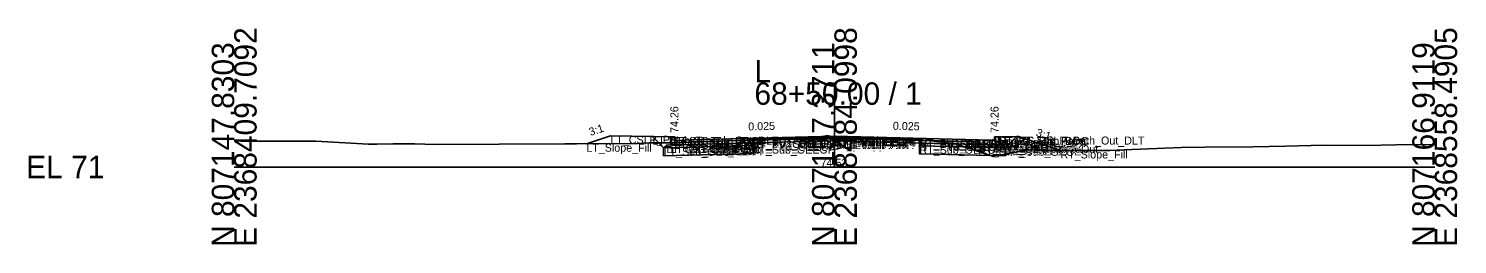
# Model space of a CAD drawing. Extents: x -26 to 8153, y -10 to 9520.
# Drawn here: x 5974.3 to 6152.8, y 8990.3 to 9017.3 of the extents above; entities that cross this region are included whole.
import ezdxf

# ---------------------------------------------------------------- set-up
doc = ezdxf.new("R2010")
doc.units = 0
for name, color, linetype in [('Exist CMT Pavement', 7, 'Continuous'), ('Exist Cross Section Cell', 7, 'Continuous'), ('Exist XS Center Line Elevation Label', 7, 'Continuous'), ('Exist XS Ground Line', 7, 'Continuous'), ('Prop CMT Conc Surface', 7, 'Continuous'), ('Prop CMT Concrete Structures', 7, 'Continuous'), ('Prop CMT Pvmt Course 1', 7, 'Continuous'), ('Prop CMT Pvmt Course 1 CG', 7, 'Continuous'), ('Prop CMT Pvmt Course 1 Wedge', 7, 'Continuous'), ('Prop CMT Pvmt Course 2', 7, 'Continuous'), ('Prop CMT Pvmt Course 2 Wedge', 7, 'Continuous'), ('Prop CMT Pvmt Course 3', 7, 'Continuous'), ('Prop CMT Pvmt Course 3 Wedge', 7, 'Continuous'), ('Prop CMT Pvmt Surface', 7, 'Continuous'), ('Prop CMT Pvmt Wedge Surface 1', 7, 'Continuous'), ('Prop CMT Pvmt Wedge Surface 2', 7, 'Continuous'), ('Prop CMT Pvmt Wedge Surface 3', 7, 'Continuous'), ('Prop CMT Shallow Undercut', 7, 'Continuous'), ('Prop CMT Shallow Undercut Boundary', 7, 'Continuous'), ('Prop CMT Slope Grass', 7, 'Continuous'), ('Prop CMT Subgrade Earthwork', 7, 'Continuous'), ('Prop XS Earthwork Shape', 7, 'Continuous'), ('Prop XS Hydro Elevations', 7, 'Continuous'), ('Prop XS SE Text', 7, 'Continuous'), ('Prop XS Side Slope Text', 7, 'Continuous'), ('Prop XS Subgrade Earthwork', 7, 'Continuous'), ('Scratch_Level_2', 7, 'Continuous'), ('Scratch_Level_6', 7, 'Continuous')]:
    doc.layers.add(name, color=color, linetype=linetype)

msp = doc.modelspace()

# ---------------------------------------------------------------- linework, layer by layer
at = {"layer": 'Exist CMT Pavement'}
for p, q in [((6064.88, 9003.4), (6065.92, 9003.41)), ((6065.92, 9003.41), (6074.99, 9003.53)), ((6074.99, 9003.53), (6084.7, 9003.46)), ((6084.7, 9003.46), (6085.62, 9003.45))]:
    msp.add_line(p, q, dxfattribs=at)
at = {"layer": 'Exist Cross Section Cell'}
for p, q in [((6075, 9000), (6075, 9010.59)), ((6000, 9000), (6075, 9000)), ((6075, 9000), (6150, 9000))]:
    msp.add_line(p, q, dxfattribs=at)
at = {"layer": 'Exist XS Ground Line'}
for p, q in [((6064.88, 9003.4), (6065.92, 9003.41)), ((6065.92, 9003.41), (6074.99, 9003.53)), ((6074.99, 9003.53), (6084.7, 9003.46)), ((6084.7, 9003.46), (6085.62, 9003.45)), ((6085.62, 9003.45), (6086.22, 9003.37)), ((6000, 9003.26), (6000.84, 9003.24)), ((6000.84, 9003.24), (6001.73, 9003.24)), ((6001.73, 9003.24), (6004.47, 9003.24)), ((6004.47, 9003.24), (6005.33, 9003.25)), ((6005.33, 9003.25), (6009.5, 9003.25)), ((6009.5, 9003.25), (6010.22, 9003.23)), ((6010.22, 9003.23), (6016.79, 9002.86)), ((6016.79, 9002.86), (6017.84, 9002.87)), ((6017.84, 9002.87), (6019.84, 9002.88)), ((6019.84, 9002.88), (6022.58, 9002.88)), ((6022.58, 9002.88), (6023.8, 9002.84)), ((6023.8, 9002.84), (6024.91, 9002.83)), ((6024.91, 9002.83), (6041.33, 9002.92)), ((6041.33, 9002.92), (6042.75, 9002.91)), ((6042.75, 9002.91), (6050.44, 9002.94)), ((6050.44, 9002.94), (6051.84, 9003.01)), ((6051.84, 9003.01), (6054.72, 9003.03)), ((6054.72, 9003.03), (6055.89, 9003.08)), ((6055.89, 9003.08), (6059.76, 9003.2)), ((6059.76, 9003.2), (6062.73, 9003.3)), ((6062.73, 9003.3), (6064.88, 9003.4)), ((6086.22, 9003.37), (6086.77, 9003.32)), ((6086.77, 9003.32), (6087.41, 9003.24)), ((6087.41, 9003.24), (6089.97, 9002.95)), ((6089.97, 9002.95), (6094.26, 9001.51)), ((6095.6, 9001.48), (6099.25, 9002.16)), ((6099.25, 9002.16), (6100.88, 9002.07)), ((6100.88, 9002.07), (6109.4, 9002.07)), ((6109.4, 9002.07), (6111.2, 9002.15)), ((6111.2, 9002.15), (6118.34, 9002.43)), ((6118.34, 9002.43), (6121.29, 9002.47)), ((6121.29, 9002.47), (6127.27, 9002.52)), ((6127.27, 9002.52), (6131.37, 9002.62)), ((6131.37, 9002.62), (6136.21, 9002.72)), ((6136.21, 9002.72), (6141.45, 9002.7)), ((6141.45, 9002.7), (6145.14, 9002.76)), ((6145.14, 9002.76), (6150, 9002.81)), ((6094.26, 9001.51), (6094.76, 9001.34)), ((6094.76, 9001.34), (6095.6, 9001.48))]:
    msp.add_line(p, q, dxfattribs=at)
at = {"layer": 'Prop CMT Conc Surface'}
for points in [[(6055, 9003.26), (6055, 9003.76), (6054.5, 9003.76)], [(6095, 9003.26), (6095, 9003.76), (6095.5, 9003.76)], [(6057, 9003.39), (6055, 9003.26)], [(6093, 9003.39), (6095, 9003.26)]]:
    msp.add_lwpolyline(points, dxfattribs=at)
at = {"layer": 'Prop CMT Concrete Structures'}
for points in [[(6057, 9003.39), (6055, 9003.26), (6055, 9003.76), (6054.5, 9003.76)], [(6054.5, 9003.76), (6054.5, 9002.75), (6057, 9002.81)], [(6093, 9003.39), (6095, 9003.26), (6095, 9003.76), (6095.5, 9003.76)], [(6095.5, 9003.76), (6095.5, 9002.75), (6093, 9002.81)], [(6057, 9002.81), (6057, 9003.39)], [(6093, 9002.81), (6093, 9003.39)]]:
    msp.add_lwpolyline(points, dxfattribs=at)
at = {"layer": 'Prop CMT Pvmt Course 1'}
for points in [[(6075, 9003.84), (6057, 9003.39)], [(6064.88, 9003.47), (6075, 9003.72)], [(6064.88, 9003.34), (6064.88, 9003.47)], [(6075, 9003.59), (6075, 9003.84)], [(6075, 9003.84), (6093, 9003.39)], [(6075, 9003.59), (6075, 9003.84)], [(6075, 9003.72), (6075, 9003.59), (6075, 9003.59)], [(6085.62, 9003.45), (6075, 9003.72)], [(6075, 9003.72), (6075, 9003.59), (6075, 9003.59)], [(6085.62, 9003.33), (6085.62, 9003.45)], [(6057, 9003.39), (6057, 9003.14)], [(6057, 9003.14), (6064.88, 9003.34)], [(6093, 9003.14), (6085.62, 9003.33)], [(6093, 9003.39), (6093, 9003.14)]]:
    msp.add_lwpolyline(points, dxfattribs=at)
at = {"layer": 'Prop CMT Pvmt Course 1 CG'}
for points in [[(6057, 9002.81), (6054, 9002.74), (6053.66, 9002.4)], [(6053.66, 9002.4), (6057, 9002.48)], [(6057, 9002.48), (6057, 9002.81)], [(6093, 9002.81), (6096, 9002.74), (6096.34, 9002.4)], [(6093, 9002.48), (6093, 9002.81)], [(6096.34, 9002.4), (6093, 9002.48)]]:
    msp.add_lwpolyline(points, dxfattribs=at)
at = {"layer": 'Prop CMT Pvmt Course 1 Wedge'}
for points in [[(6075, 9003.72), (6064.88, 9003.47)], [(6075, 9003.72), (6085.62, 9003.45)]]:
    msp.add_lwpolyline(points, dxfattribs=at)
at = {"layer": 'Prop CMT Pvmt Course 2'}
for points in [[(6064.88, 9003.34), (6057, 9003.14)], [(6057, 9003.14), (6057, 9002.81)], [(6057, 9002.81), (6064.88, 9003.01)], [(6064.88, 9003.01), (6064.88, 9003.34)], [(6085.62, 9003), (6085.62, 9003.33)], [(6085.62, 9003.33), (6093, 9003.14)], [(6093, 9002.81), (6085.62, 9003)], [(6093, 9003.14), (6093, 9002.81)]]:
    msp.add_lwpolyline(points, dxfattribs=at)
at = {"layer": 'Prop CMT Pvmt Course 2 Wedge'}
for points in [[(6075, 9003.59), (6064.88, 9003.34)], [(6075, 9003.59), (6085.62, 9003.33)]]:
    msp.add_lwpolyline(points, dxfattribs=at)
at = {"layer": 'Prop CMT Pvmt Course 3'}
for points in [[(6064.88, 9003.01), (6057, 9002.81)], [(6057, 9002.81), (6057, 9002.48)], [(6057, 9002.48), (6064.88, 9002.68)], [(6064.88, 9002.68), (6064.88, 9003.01)], [(6085.62, 9003), (6093, 9002.81)], [(6085.62, 9002.66), (6085.62, 9003)], [(6093, 9002.48), (6085.62, 9002.66)], [(6093, 9002.81), (6093, 9002.48)]]:
    msp.add_lwpolyline(points, dxfattribs=at)
at = {"layer": 'Prop CMT Pvmt Course 3 Wedge'}
for points in [[(6075, 9003.26), (6064.88, 9003.01)], [(6075, 9003.26), (6085.62, 9003)]]:
    msp.add_lwpolyline(points, dxfattribs=at)
at = {"layer": 'Prop CMT Pvmt Surface'}
for points in [[(6075, 9003.84), (6057, 9003.39)], [(6075, 9003.84), (6093, 9003.39)]]:
    msp.add_lwpolyline(points, dxfattribs=at)
at = {"layer": 'Prop CMT Pvmt Wedge Surface 1'}
for points in [[(6075, 9003.72), (6064.88, 9003.47)], [(6064.88, 9003.47), (6064.88, 9003.34)], [(6075, 9003.72), (6085.62, 9003.45)], [(6085.62, 9003.45), (6085.62, 9003.33)], [(6057, 9003.14), (6057, 9003.39)], [(6064.88, 9003.34), (6057, 9003.14)], [(6085.62, 9003.33), (6093, 9003.14)], [(6093, 9003.14), (6093, 9003.39)]]:
    msp.add_lwpolyline(points, dxfattribs=at)
at = {"layer": 'Prop CMT Pvmt Wedge Surface 2'}
for points in [[(6075, 9003.59), (6057, 9003.14)], [(6075, 9003.59), (6093, 9003.14)], [(6057, 9003.14), (6057, 9003.39)], [(6093, 9003.14), (6093, 9003.39)]]:
    msp.add_lwpolyline(points, dxfattribs=at)
at = {"layer": 'Prop CMT Pvmt Wedge Surface 3'}
for points in [[(6057, 9002.81), (6057, 9003.39)], [(6075, 9003.26), (6057, 9002.81)], [(6075, 9003.26), (6093, 9002.81)], [(6093, 9002.81), (6093, 9003.39)]]:
    msp.add_lwpolyline(points, dxfattribs=at)
at = {"layer": 'Prop CMT Shallow Undercut'}
for p, q in [((6064.88, 9002.68), (6053.66, 9002.4)), ((6053.66, 9002.4), (6053.66, 9001.4)), ((6053.66, 9001.4), (6064.88, 9001.68)), ((6064.88, 9001.68), (6064.88, 9002.68))]:
    msp.add_line(p, q, dxfattribs=at)
for points in [[(6085.62, 9001.66), (6094.46, 9001.44), (6094.26, 9001.51), (6091.23, 9002.52), (6085.62, 9002.66)], [(6095.6, 9001.48), (6096.34, 9001.62), (6096.34, 9001.4), (6095.25, 9001.42)]]:
    msp.add_lwpolyline(points, close=True, dxfattribs=at)
at = {"layer": 'Prop CMT Shallow Undercut Boundary'}
for p, q in [((6053.66, 9002.4), (6053.66, 9001.4)), ((6053.66, 9001.4), (6064.88, 9001.68)), ((6064.88, 9002.68), (6064.88, 9001.68)), ((6085.62, 9002.66), (6085.62, 9001.66)), ((6085.62, 9001.66), (6096.34, 9001.4)), ((6096.34, 9002.4), (6096.34, 9001.4))]:
    msp.add_line(p, q, dxfattribs=at)
at = {"layer": 'Prop CMT Slope Grass'}
for points in [[(6054.5, 9003.76), (6047, 9003.91), (6044, 9002.91)], [(6095.5, 9003.76), (6098, 9003.81), (6103.24, 9002.07)]]:
    msp.add_lwpolyline(points, dxfattribs=at)
at = {"layer": 'Prop CMT Subgrade Earthwork'}
for points in [[(6057, 9002.48), (6053.66, 9002.4), (6052.25, 9003.81)], [(6085.62, 9002.66), (6085.6, 9003.45)], [(6093, 9002.48), (6096.34, 9002.4), (6097.75, 9003.81)], [(6064.88, 9002.68), (6057, 9002.48)], [(6064.88, 9002.68), (6064.9, 9003.4)], [(6085.62, 9002.66), (6093, 9002.48)]]:
    msp.add_lwpolyline(points, dxfattribs=at)
at = {"layer": 'Prop XS Earthwork Shape'}
for points in [[(6052.25, 9003.81), (6047, 9003.91), (6044, 9002.91), (6050.44, 9002.94), (6051.84, 9003.01), (6053.04, 9003.02)], [(6086.22, 9003.37), (6086.77, 9003.32), (6087.41, 9003.24), (6089.97, 9002.95), (6091.23, 9002.52), (6085.62, 9002.66), (6085.6, 9003.45), (6085.62, 9003.45)], [(6097.75, 9003.81), (6098, 9003.81), (6103.24, 9002.07), (6100.88, 9002.07), (6099.25, 9002.16), (6096.34, 9001.62), (6096.34, 9002.4)], [(6059.76, 9003.2), (6062.73, 9003.3), (6064.88, 9003.4), (6064.9, 9003.4), (6064.88, 9002.68), (6057, 9002.48), (6053.66, 9002.4), (6053.04, 9003.02), (6054.72, 9003.03), (6055.89, 9003.08)], [(6057, 9002.48), (6053.66, 9002.4), (6053.66, 9001.4), (6064.88, 9001.68), (6064.88, 9002.68)], [(6085.62, 9002.66), (6085.62, 9001.66), (6094.46, 9001.44), (6094.26, 9001.51), (6091.23, 9002.52)], [(6095.25, 9001.42), (6095.6, 9001.48), (6096.34, 9001.62), (6096.34, 9002.4), (6093, 9002.48), (6091.23, 9002.52), (6094.26, 9001.51), (6094.46, 9001.44)], [(6095.25, 9001.42), (6096.34, 9001.4), (6096.34, 9001.62), (6095.6, 9001.48)], [(6094.76, 9001.34), (6095.25, 9001.42), (6094.46, 9001.44)]]:
    msp.add_lwpolyline(points, close=True, dxfattribs=at)
at = {"layer": 'Prop XS Subgrade Earthwork'}
for p, q in [((6053.66, 9002.4), (6064.88, 9002.68)), ((6085.62, 9002.66), (6096.34, 9002.4))]:
    msp.add_line(p, q, dxfattribs=at)
at = {"layer": 'Scratch_Level_6'}
for p, q in [((6064.88, 9002.68), (6053.66, 9002.4)), ((6053.66, 9002.4), (6053.66, 9001.4)), ((6053.66, 9001.4), (6064.88, 9001.68)), ((6064.88, 9001.68), (6064.88, 9002.68))]:
    msp.add_line(p, q, dxfattribs=at)
for points in [[(6085.62, 9001.66), (6094.46, 9001.44), (6094.26, 9001.51), (6091.23, 9002.52), (6085.62, 9002.66)], [(6095.6, 9001.48), (6096.34, 9001.62), (6096.34, 9001.4), (6095.25, 9001.42)]]:
    msp.add_lwpolyline(points, close=True, dxfattribs=at)

# ---------------------------------------------------------------- texts
at = {"layer": 'Exist Cross Section Cell'}
for s, p in [('E 2368409.7092', (6002.8, 8990)), ('E 2368484.0998', (6077.8, 8990)), ('E 2368558.4905', (6152.8, 8990)), ('N 807147.8303', (6000, 8990)), ('N 807157.3711', (6075, 8990)), ('N 807166.9119', (6150, 8990))]:
    msp.add_text(s, height=2.8, rotation=90, dxfattribs=at).set_placement(p)
for s, p in [('L', (6065, 9010.59)), ('68+50.00 / 1', (6065, 9007.79)), ('EL 71', (5974, 8998.6))]:
    msp.add_text(s, height=2.8, dxfattribs=at).set_placement(p)
at = {"layer": 'Exist XS Center Line Elevation Label'}
msp.add_text('74.53', height=1, dxfattribs=at).set_placement((6073.27, 9000.03))
at = {"layer": 'Prop XS Hydro Elevations'}
for p in [(6055.5, 9004.26), (6095.5, 9004.26)]:
    msp.add_text('74.26', height=1, rotation=90, dxfattribs=at).set_placement(p)
at = {"layer": 'Prop XS SE Text'}
for rotation, p in [(1.4321, (6064.24, 9004.57)), (358.5679, (6082.29, 9004.66))]:
    msp.add_text('0.025', height=1, rotation=rotation, dxfattribs=at).set_placement(p)
at = {"layer": 'Prop XS Side Slope Text'}
for rotation, p in [(18.4349, (6044.51, 9003.87)), (341.5651, (6100.1, 9003.9))]:
    msp.add_text('3:1', height=1, rotation=rotation, dxfattribs=at).set_placement(p)
at = {"layer": 'Scratch_Level_2'}
for s, p in [('LT_CSLP_Pnt', (6047, 9002.91)), ('LT_Sub_Trench_Out_DLT', (6052.25, 9002.81)), ('LT_CG_Top_BOC', (6054.5, 9002.76)), ('LT_CG_Top_Face', (6055, 9002.76)), ('LT_PV1_OEOT', (6057, 9002.39)), ('LT_PV1_OEEOP', (6064.88, 9002.47)), ('LT_PV_OEEOP_EG', (6064.88, 9002.4)), ('LT_PV_Sub_Tie_Out', (6064.9, 9002.4)), ('PV1_PGL', (6075, 9002.84)), ('RT_PV1_IEEOP', (6075, 9002.72)), ('LT_PV1_IEEOP', (6075, 9002.72)), ('RT_PV2_IEEOP', (6075, 9002.59)), ('LT_PV2_IEEOP', (6075, 9002.59)), ('PV2_PGL', (6075, 9002.59)), ('RT_PV_IEEOP_EG', (6075, 9002.53)), ('LT_PV_IEEOP_EG', (6075, 9002.53)), ('RT_PV_Sub_Tie_Out', (6085.6, 9002.45)), ('RT_PV_OEEOP_EG', (6085.62, 9002.45)), ('RT_PV1_OEEOP', (6085.62, 9002.45)), ('RT_PV1_OEOT', (6093, 9002.39)), ('RT_CG_Top_Face', (6095, 9002.76)), ('RT_CG_Top_BOC', (6095.5, 9002.76)), ('RT_Sub_Trench_Out_DLT', (6097.75, 9002.81)), ('RT_CSLP_Pnt', (6098, 9002.81)), ('LT_Slope_Fill', (6044, 9001.91)), ('LT_Sub_OEOP', (6053.66, 9001.4)), ('LT_CG1_Shelf_Out', (6054, 9001.74)), ('LT_CG_Bot_BOC', (6054.5, 9001.75)), ('LT_CG_Top_Gut', (6055, 9002.26)), ('LT_PV2_OEOT', (6057, 9002.14)), ('LT_PV3_OEOT', (6057, 9001.81)), ('LT_CG_Bot_IE', (6057, 9001.81)), ('LT_Sub_OEOT', (6057, 9001.48)), ('LT_PV2_OEEOP', (6064.88, 9002.34)), ('LT_PV3_OEEOP', (6064.88, 9002.01)), ('LT_Sub_OEEOP', (6064.88, 9001.68)), ('RT_PV3_IEEOP', (6075, 9002.26)), ('LT_PV3_IEEOP', (6075, 9002.26)), ('RT_PV2_OEEOP', (6085.62, 9002.33)), ('RT_PV3_OEEOP', (6085.62, 9002)), ('RT_Sub_OEEOP', (6085.62, 9001.66)), ('RT_PV2_OEOT', (6093, 9002.14)), ('RT_PV3_OEOT', (6093, 9001.81)), ('RT_CG_Bot_IE', (6093, 9001.81)), ('RT_Sub_OEOT', (6093, 9001.48)), ('RT_CG_Top_Gut', (6095, 9002.26)), ('RT_CG_Bot_BOC', (6095.5, 9001.75)), ('RT_CG1_Shelf_Out', (6096, 9001.74)), ('RT_Sub_OEOP', (6096.34, 9001.4)), ('RT_Slope_Fill', (6103.24, 9001.07))]:
    msp.add_text(s, height=1, dxfattribs=at).set_placement(p)

doc.saveas('drawing.dxf')
